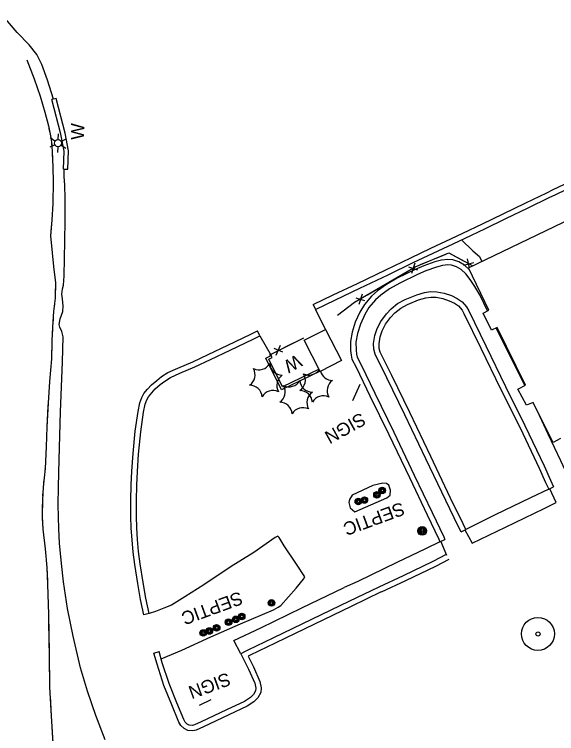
# Model space of a CAD drawing. Extents: x 353423 to 364002, y 127000 to 201942.
# Drawn here: x 358103.2 to 358350.6, y 132514.4 to 132842.4 of the extents above; entities that cross this region are included whole.
import ezdxf

# ---------------------------------------------------------------- set-up
doc = ezdxf.new("R2010")
doc.units = 0
for name, color, linetype in [('E_DTM_SlopeBottom', 7, 'Continuous'), ('E_FEN_Generic', 7, 'Continuous'), ('E_LAND_BrushLine', 7, 'Continuous'), ('E_MISCPROP', 7, 'Continuous'), ('E_RDWY_AsphConc', 7, 'Continuous'), ('E_STRUCT_WingWall', 7, 'Continuous'), ('E_UTL_ETransformer', 7, 'Continuous'), ('E_WTR_FlowLine', 7, 'Continuous')]:
    doc.layers.add(name, color=color, linetype=linetype)

msp = doc.modelspace()

# ---------------------------------------------------------------- linework, layer by layer
at = {"layer": 'E_DTM_SlopeBottom'}
for p, q in [((358309.75, 132730.89), (358310.73, 132726.78)), ((358283.04, 132727.29), (358287.06, 132725.97)), ((358284.53, 132724.41), (358286.1, 132729.08)), ((358308.08, 132728.11), (358312.88, 132729.23)), ((358260.49, 132710.34), (358262.06, 132715.01)), ((358259, 132713.22), (358263.01, 132711.9)), ((358224.4, 132691.39), (358222.52, 132686.83)), ((358225.69, 132688.42), (358221.78, 132690.01))]:
    msp.add_line(p, q, dxfattribs=at)
for points in [[(358125.56, 132771.9), (358127.55, 132771.82), (358127.89, 132780.13), (358126.39, 132788.2), (358122.22, 132804.08), (358120.29, 132803.58)], [(358125.56, 132771.9), (358125.89, 132779.99), (358124.44, 132787.76), (358120.29, 132803.58)], [(358250.63, 132705.29), (358258.41, 132711.14), (358286.06, 132727.32), (358301.4, 132733.63), (358312.39, 132727.79)], [(358298.97, 132732.63), (358301.4, 132733.63), (358307.87, 132730.19)], [(358288.49, 132728.32), (358298.97, 132732.63)], [(358274.06, 132720.3), (358282.65, 132725.33)], [(358264.29, 132714.58), (358274.06, 132720.3)], [(358250.63, 132705.29), (358258.41, 132711.14), (358258.61, 132711.25)], [(358235.12, 132694.79), (358219.65, 132687.08)], [(358235.12, 132694.79), (358226.21, 132690.35)], [(358220.32, 132687.41), (358219.65, 132687.08)], [(358242.68, 132679.75), (358225.08, 132671.21), (358218.01, 132685.68), (358220.35, 132686.82)], [(358242.23, 132680.64), (358225.54, 132672.54), (358219.35, 132685.22), (358220.79, 132685.92), (358220.35, 132686.82)]]:
    msp.add_lwpolyline(points, dxfattribs=at)
at = {"layer": 'E_FEN_Generic'}
for centre, start, end in [((358207.31, 132678.04), 304.2311, 29.996), ((358214.76, 132686.06), 244.2311, 329.996), ((358225.42, 132683.62), 184.2311, 269.996), ((358228.64, 132673.16), 124.2311, 209.996), ((358230.24, 132675.64), 304.2311, 29.996), ((358237.68, 132683.66), 244.2311, 324.9664), ((358248.35, 132681.22), 195.6548, 269.996), ((358228.49, 132678.28), 244.2311, 329.996), ((358239.16, 132675.84), 184.2311, 269.996), ((358251.57, 132670.76), 124.2311, 209.996), ((358210.53, 132667.59), 4.2311, 89.996), ((358221.2, 132665.15), 64.2311, 149.996), ((358221.05, 132670.26), 304.2311, 29.996), ((358233.45, 132665.18), 4.2311, 89.996), ((358242.38, 132665.38), 124.2311, 209.996), ((358244.12, 132662.74), 64.2311, 149.996), ((358224.27, 132659.8), 4.2311, 89.996), ((358234.93, 132657.36), 64.2311, 149.996)]:
    msp.add_arc(centre, 5.72, start, end, dxfattribs=at)
at = {"layer": 'E_LAND_BrushLine'}
for p, q in [((358121.71, 132784.66), (358119.51, 132786.06)), ((358123.17, 132785.37), (358123.28, 132787.89)), ((358124.6, 132784.46), (358126.8, 132785.67)), ((358121.68, 132782.96), (358119.35, 132781.8)), ((358124.53, 132782.83), (358126.7, 132781.43)), ((358123.03, 132782.1), (358122.91, 132779.49))]:
    msp.add_line(p, q, dxfattribs=at)
for points in [[(358257.56, 132666.41), (358261, 132673.76)], [(358192.82, 132529.77), (358187.52, 132527.17)]]:
    msp.add_lwpolyline(points, dxfattribs=at)
for centre, radius in [((358123.12, 132783.73), 1.64), ((358289.27, 132606.88), 2.02), ((358289.26, 132606.88), 1.52), ((358289.3, 132606.88), 1.01), ((358289.29, 132606.89), 0.502)]:
    msp.add_circle(centre, radius, dxfattribs=at)
at = {"layer": 'E_MISCPROP'}
for points in [[(358121.04, 132803.77), (358118.31, 132812.41), (358115.69, 132819.53), (358113.54, 132824.21), (358109.97, 132828.52), (358104.47, 132834.22), (358097.51, 132842.43)], [(358349.06, 132762.58), (358353.93, 132764.89), (358364.31, 132769.86), (358374.69, 132775.32), (358385.91, 132780.9), (358398.31, 132787.41)], [(358350.19, 132760.35), (358355.01, 132762.63), (358365.43, 132767.63), (358375.83, 132773.1), (358387.04, 132778.68), (358399.47, 132785.2)], [(358125.68, 132583.63), (358124.69, 132591.98), (358123.84, 132601.24), (358123.45, 132607.8), (358123.15, 132618.76), (358123.28, 132626.98), (358123.71, 132639.38), (358124.23, 132661.2), (358125.18, 132683.94), (358125.43, 132695.39), (358124.88, 132697.8), (358123.98, 132699.72), (358123.71, 132701.05), (358124.11, 132703.62), (358125.31, 132706.97), (358125.46, 132709.29), (358125.16, 132712.74), (358124.93, 132714.9), (358125.13, 132717.22), (358125.56, 132719), (358125.9, 132723.23), (358126.19, 132738.95), (358126.33, 132748.46), (358126.32, 132758.42), (358126.22, 132764.56), (358126.01, 132768.54), (358125.93, 132771.88)], [(358307.76, 132742.63), (358316.71, 132746.94), (358326.27, 132751.54), (358336.58, 132756.51), (358346.15, 132761.1), (358349.06, 132762.58)], [(358308.83, 132740.37), (358317.79, 132744.68), (358327.36, 132749.29), (358337.67, 132754.26), (358347.26, 132758.86), (358350.19, 132760.35)], [(358239.57, 132710.09), (358248.66, 132714.48), (358259.8, 132719.77), (358272.69, 132725.9), (358284.13, 132731.45), (358293.15, 132735.74), (358302.26, 132740.03), (358307.76, 132742.63)], [(358239.57, 132710.09), (358240.66, 132707.84), (358249.74, 132712.22), (358260.88, 132717.51), (358273.77, 132723.64), (358285.21, 132729.2), (358294.22, 132733.48), (358303.33, 132737.77), (358308.83, 132740.37)], [(358307.24, 132739.62), (358312.42, 132734.58), (358315.38, 132731.94), (358316.49, 132729.77)], [(358310.86, 132725.92), (358308.56, 132728.03), (358306.03, 132729.57), (358303.19, 132730.5), (358300.97, 132730.66), (358298.11, 132730.35), (358295.01, 132729.58), (358290.01, 132727.75), (358286.11, 132726.04), (358277.83, 132722.09), (358272.95, 132719.3), (358268.81, 132716.36), (358266.16, 132713.94), (358262.96, 132710.15), (358260.82, 132706.67), (358258.75, 132702.07), (358257.27, 132697.5), (358256.55, 132693.2), (358256.59, 132689.18), (358256.82, 132687.05), (358257.24, 132685.21), (358259.17, 132681.53), (358265.34, 132668.53), (358274.03, 132650.79), (358283.41, 132631.23), (358291.56, 132614.26), (358296.83, 132603.09), (358297.31, 132601.93), (358299.62, 132602.89)], [(358319.13, 132707.25), (358315.54, 132714.51), (358313.27, 132718.37), (358311.19, 132721.55), (358309.17, 132724.08), (358307.05, 132726.02), (358304.98, 132727.28), (358302.71, 132728.03), (358301.02, 132728.15), (358298.55, 132727.88), (358295.74, 132727.18), (358290.95, 132725.43), (358287.15, 132723.77), (358278.99, 132719.87), (358274.3, 132717.19), (358270.38, 132714.42), (358267.97, 132712.21), (358264.99, 132708.68), (358263.03, 132705.49), (358261.09, 132701.17), (358259.71, 132696.9), (358259.05, 132693), (358259.09, 132689.33), (358259.29, 132687.47), (358259.6, 132686.09), (358261.41, 132682.65), (358267.59, 132669.61), (358276.28, 132651.89), (358285.66, 132632.31), (358293.82, 132615.33), (358299.12, 132604.1), (358299.62, 132602.89)], [(358307, 132606.38), (358305.69, 132608.98), (358300, 132620.76), (358290.95, 132639.66), (358281.33, 132659.76), (358273.09, 132676.65), (358267.82, 132687.45), (358267.19, 132689.72), (358267.07, 132692.34), (358267.62, 132696.05), (358268.76, 132699.13), (358270.45, 132702.43), (358272.93, 132705.82), (358275.04, 132708.11), (358278.06, 132710.53), (358281.52, 132712.41), (358286.76, 132714.6), (358290.34, 132715.63), (358293.05, 132716.02), (358295.97, 132715.94), (358299.28, 132715.27), (358302.58, 132714.16), (358305.22, 132712.9), (358307.51, 132711.35), (358309.47, 132709.01), (358310.53, 132707.25), (358318.24, 132691.27), (358327.29, 132672.76), (358336.15, 132654.93), (358344.86, 132636.58), (358347.73, 132630.01), (358349.21, 132627)], [(358307, 132606.38), (358309.23, 132607.5), (358307.93, 132610.08), (358302.25, 132621.84), (358293.2, 132640.74), (358283.58, 132660.85), (358275.34, 132677.74), (358270.16, 132688.34), (358269.67, 132690.12), (358269.57, 132692.21), (358270.05, 132695.43), (358271.05, 132698.12), (358272.59, 132701.11), (358274.86, 132704.23), (358276.75, 132706.28), (358279.45, 132708.44), (358282.6, 132710.15), (358287.59, 132712.24), (358290.86, 132713.18), (358293.2, 132713.51), (358295.68, 132713.45), (358298.63, 132712.85), (358301.64, 132711.84), (358303.97, 132710.72), (358305.82, 132709.48), (358307.43, 132707.55), (358308.33, 132706.05), (358315.99, 132690.18), (358325.05, 132671.66), (358333.91, 132653.84), (358342.58, 132635.54), (358345.46, 132628.95), (358346.97, 132625.89), (358349.21, 132627)], [(358240.66, 132707.84), (358243.34, 132702.21), (358245.11, 132698.76)], [(358159.48, 132582.92), (358158.17, 132591.49), (358157.38, 132597.24), (358156.89, 132602.8), (358156.57, 132608.08), (358156.37, 132613.56), (358156.42, 132620.75), (358156.53, 132627.84), (358156.85, 132634.1), (358157.43, 132642.12), (358158.4, 132652.42), (358159.67, 132661.39), (358160.45, 132665.3), (358161.31, 132667.66), (358162.33, 132669.46), (358163.99, 132671.54), (358165.78, 132673.44), (358168.15, 132675.53), (358170.4, 132677.22), (358173.3, 132679.05), (358177.72, 132681.03), (358184.56, 132683.99), (358191.61, 132687.31), (358200.66, 132691.59), (358211.02, 132696.56), (358214.16, 132698.05)], [(358161.95, 132583.3), (358160.65, 132591.85), (358159.87, 132597.52), (358159.38, 132602.99), (358159.06, 132608.2), (358158.87, 132613.59), (358158.92, 132620.73), (358159.03, 132627.76), (358159.34, 132633.94), (358159.92, 132641.92), (358160.88, 132652.12), (358162.14, 132660.97), (358162.87, 132664.63), (358163.58, 132666.61), (358164.41, 132668.05), (358165.89, 132669.9), (358167.52, 132671.64), (358169.72, 132673.58), (358171.82, 132675.16), (358174.48, 132676.84), (358178.73, 132678.74), (358185.59, 132681.71), (358192.68, 132685.05), (358201.74, 132689.33), (358212.1, 132694.3), (358215.23, 132695.79), (358214.16, 132698.05)], [(358336.04, 132673.13), (358322.99, 132699.46)], [(358215.23, 132695.79), (358220.35, 132686.82)], [(358356.48, 132630.37), (358355.81, 132631.7), (358352.52, 132638.85), (358346.75, 132650.94), (358342.83, 132659.44), (358339.86, 132665.43)], [(358308.79, 132607.28), (358312.02, 132601.2), (358327.27, 132608.57), (358344.96, 132617.14), (358350.34, 132619.78), (358347.42, 132626.12)], [(358346.97, 132625.89), (358338.75, 132621.88), (358322.57, 132614.12), (358311.3, 132608.64), (358309.23, 132607.5)], [(358235.72, 132585.91), (358231.85, 132591.76), (358226.33, 132600.1), (358223.98, 132603.9), (358223.47, 132604.45), (358222.15, 132603.91), (358212.44, 132597), (358202.19, 132590.56), (358189.67, 132582.27), (358180.95, 132576.76), (358174.84, 132573.02), (358171.47, 132571.68), (358167.63, 132570.05), (358164.66, 132569.19)], [(358297.31, 132601.93), (358290.76, 132598.68), (358277.66, 132592.52), (358259.93, 132583.83), (358253.72, 132580.98)], [(358300.48, 132595.66), (358297.77, 132602.12)], [(358300.25, 132596.11), (358294.17, 132592.9), (358280.54, 132586.41), (358269.49, 132581.27)], [(358301.42, 132593.89), (358295.29, 132590.66), (358281.6, 132584.15), (358270.55, 132579)], [(358170.2, 132548.46), (358179.55, 132552.48), (358192.86, 132558.6), (358206.43, 132564.54), (358221.45, 132570.86), (358223.59, 132572.04), (358224.78, 132572.84), (358231.73, 132580.74), (358235.16, 132584.89), (358235.72, 132585.91)], [(358144.66, 132511.56), (358140.32, 132522.65), (358136.56, 132533.82), (358133.41, 132544.48), (358129.98, 132558.88), (358127.42, 132571.45), (358125.68, 132583.63)], [(358164.66, 132569.19), (358162.21, 132568.66), (358160.72, 132575.65), (358159.48, 132582.89)], [(358164.66, 132569.19), (358163.17, 132576.12), (358161.95, 132583.31)], [(358270.57, 132579.01), (358256.83, 132572.38), (358240.1, 132564.38), (358222.17, 132555.7), (358210.86, 132550.27), (358209.85, 132549.71), (358212.26, 132544.81), (358215.25, 132538.14), (358215.84, 132535.27), (358215.7, 132533.15), (358214.35, 132530.73), (358212.49, 132528.89), (358209.39, 132526.94), (358201, 132523), (358189.55, 132517.54), (358186.12, 132515.97), (358184.57, 132515.67), (358182.31, 132515.81), (358180.62, 132516.7), (358179.2, 132518.08), (358178.28, 132519.67), (358175.01, 132527.49), (358171.46, 132536.39), (358168.31, 132546.03), (358166.8, 132551.18), (358169.21, 132551.88)], [(358269.49, 132581.26), (358255.74, 132574.64), (358239.01, 132566.63), (358221.08, 132557.95), (358209.72, 132552.49), (358208.57, 132551.86), (358206.5, 132550.85), (358209.99, 132543.75), (358212.86, 132537.36), (358213.33, 132535.1), (358213.24, 132533.87), (358212.34, 132532.25), (358210.93, 132530.86), (358208.18, 132529.14), (358199.93, 132525.26), (358188.49, 132519.81), (358185.35, 132518.37), (358184.41, 132518.18), (358183.01, 132518.27), (358182.1, 132518.75), (358181.19, 132519.63), (358180.53, 132520.78), (358177.32, 132528.43), (358173.82, 132537.24), (358170.7, 132546.77), (358169.21, 132551.88)], [(358206.5, 132550.85), (358203.35, 132556.91), (358215.6, 132562.65), (358234.34, 132571.75), (358253.72, 132580.98)]]:
    msp.add_lwpolyline(points, dxfattribs=at)
for points in [[(358219.33, 132573.87), (358219.41, 132574.42), (358219.59, 132574.68), (358220.06, 132575.06), (358220.61, 132575.18), (358221.08, 132575.14), (358221.5, 132574.83), (358221.88, 132574.24), (358221.88, 132573.51), (358221.53, 132573.05), (358220.72, 132572.67), (358220.04, 132572.76), (358219.58, 132573.1)], [(358199.82, 132565.03), (358199.91, 132565.58), (358200.09, 132565.84), (358200.56, 132566.22), (358201.11, 132566.34), (358201.58, 132566.3), (358202, 132565.99), (358202.38, 132565.4), (358202.37, 132564.67), (358202.03, 132564.21), (358201.22, 132563.83), (358200.54, 132563.92), (358200.07, 132564.26)], [(358194.4, 132562.52), (358194.49, 132563.07), (358194.66, 132563.32), (358195.14, 132563.7), (358195.69, 132563.83), (358196.16, 132563.78), (358196.58, 132563.48), (358196.96, 132562.88), (358196.95, 132562.16), (358196.61, 132561.69), (358195.8, 132561.32), (358195.12, 132561.41), (358194.65, 132561.75)]]:
    msp.add_lwpolyline(points, close=True, dxfattribs=at)
at = {"layer": 'E_RDWY_AsphConc'}
for radius in [7.5, 7.5, 7.5, 7.5, 0.96, 0.96, 0.96, 0.96]:
    msp.add_circle((358342.07, 132559.87), radius, dxfattribs=at)
at = {"layer": 'E_STRUCT_WingWall'}
for points in [[(358108.92, 132821.77), (358112.23, 132813.06), (358114.97, 132805.07), (358117.09, 132797.78), (358118.72, 132791.66), (358120.07, 132785.55), (358120.47, 132780.02), (358120.8, 132772.59), (358120.86, 132766.16), (358120.75, 132756.2), (358120.38, 132748.61), (358119.72, 132741.44), (358120.42, 132733.67), (358121.1, 132727.48), (358121.94, 132719.96), (358121.86, 132713.03), (358121.09, 132706.89), (358120.68, 132699.76), (358120.36, 132693.5), (358120.15, 132685.41), (358119.29, 132675.04), (358118.57, 132665.13), (358117.99, 132654.35), (358117.73, 132645.22), (358117.21, 132635.27), (358116.33, 132626.85), (358116.02, 132621), (358115.85, 132613.49), (358116.2, 132607.64), (358117.27, 132598.75), (358118.01, 132590.23), (358118.4, 132582.5)], [(358108.92, 132821.77), (358112.23, 132813.06), (358114.97, 132805.07), (358117.09, 132797.78), (358118.03, 132794.26)], [(358119.01, 132790.38), (358119.43, 132788.43)], [(358120.14, 132784.5), (358120.29, 132782.51)], [(358120.53, 132778.51), (358120.62, 132776.52)], [(358120.8, 132772.52), (358120.86, 132766.16), (358120.75, 132756.2), (358120.38, 132748.61), (358119.91, 132743.55)], [(358119.91, 132743.55), (358119.72, 132741.44), (358120.42, 132733.67), (358121.1, 132727.48), (358121.94, 132719.96), (358121.88, 132714.67)], [(358121.57, 132710.69), (358121.32, 132708.71)], [(358120.97, 132704.73), (358120.85, 132702.73)], [(358120.63, 132698.74), (358120.53, 132696.74)], [(358120.35, 132692.74), (358120.15, 132685.41), (358119.29, 132675.04), (358118.57, 132665.13), (358118.49, 132663.81)], [(358118.49, 132663.81), (358117.99, 132654.35), (358117.73, 132645.22), (358117.21, 132635.27), (358117.16, 132634.84)], [(358116.75, 132630.86), (358116.54, 132628.88)], [(358116.22, 132624.89), (358116.12, 132622.89)], [(358115.97, 132618.89), (358115.92, 132616.89)], [(358115.89, 132612.9), (358116.2, 132607.64), (358117.27, 132598.75), (358118.01, 132590.23), (358118.33, 132584.01)], [(358118.33, 132584.01), (358118.4, 132582.5)], [(358118.4, 132582.5), (358118.73, 132568.67), (358119.04, 132551.36), (358119.27, 132535.53), (358119.98, 132522.51), (358121.21, 132502.38), (358121.74, 132481.96), (358121.21, 132466.01), (358121.37, 132453.16), (358121.65, 132444.1), (358121.43, 132425), (358121.9, 132412.02), (358121.73, 132399.64), (358122.31, 132385.43), (358122.83, 132374.45), (358123.01, 132364.33), (358122.13, 132354.08), (358122.06, 132343.75), (358122.64, 132335.19), (358122.89, 132328.51), (358123.75, 132323.66), (358124.74, 132319.35), (358127.11, 132317.04), (358130.2, 132315.27)], [(358118.4, 132582.5), (358118.73, 132568.67), (358119, 132553.51)], [(358119.06, 132549.51), (358119.09, 132547.51)], [(358119.15, 132543.51), (358119.18, 132541.51)], [(358119.24, 132537.51), (358119.27, 132535.53), (358119.27, 132535.51)], [(358119.49, 132531.52), (358119.98, 132522.51), (358121.2, 132502.57)]]:
    msp.add_lwpolyline(points, dxfattribs=at)
at = {"layer": 'E_UTL_ETransformer'}
for centre, radius in [((358271.06, 132625.33), 1.5), ((358271.06, 132625.34), 1.22), ((358271.08, 132625.33), 0.968), ((358271.08, 132625.3), 0.605), ((358260.13, 132620.22), 1.5), ((358262.88, 132620.94), 1.5), ((358262.88, 132620.94), 1.22), ((358262.89, 132620.94), 0.968), ((358268.63, 132623.29), 1.5), ((358268.63, 132623.29), 1.22), ((358268.65, 132623.28), 0.968), ((358268.65, 132623.26), 0.605), ((358260.13, 132620.23), 1.22), ((358260.15, 132620.22), 0.968), ((358260.15, 132620.19), 0.605), ((358262.9, 132620.91), 0.605), ((358220.5, 132574.01), 1.5), ((358220.51, 132574.02), 1.22), ((358220.52, 132574.01), 0.968), ((358220.53, 132573.98), 0.605), ((358206.93, 132567.85), 1.5), ((358200.92, 132565.26), 1.5), ((358200.92, 132565.26), 1.22), ((358200.93, 132565.25), 0.968), ((358204.2, 132566.55), 1.5), ((358204.2, 132566.56), 1.22), ((358204.22, 132566.55), 0.968), ((358204.22, 132566.52), 0.605), ((358206.94, 132567.86), 1.22), ((358206.95, 132567.85), 0.968), ((358206.96, 132567.82), 0.605), ((358192.17, 132561.23), 1.5), ((358195.5, 132562.66), 1.5), ((358195.5, 132562.66), 1.22), ((358195.51, 132562.65), 0.968), ((358195.52, 132562.63), 0.605), ((358200.94, 132565.23), 0.605), ((358189.4, 132560.32), 1.5), ((358189.4, 132560.32), 1.22), ((358189.41, 132560.31), 0.968), ((358189.42, 132560.29), 0.605), ((358192.17, 132561.24), 1.22), ((358192.18, 132561.23), 0.968), ((358192.19, 132561.2), 0.605)]:
    msp.add_circle(centre, radius, dxfattribs=at)
at = {"layer": 'E_WTR_FlowLine'}
msp.add_lwpolyline([(358352.35, 132648.94), (358349.01, 132647.24), (358339.95, 132665.47), (358336.9, 132664.2), (358332.95, 132671.44), (358336.35, 132673.3), (358323.4, 132699.66), (358320.9, 132698.43), (358317.12, 132706.16), (358319.73, 132707.58), (358310.42, 132726.84), (358361.28, 132751.37)], dxfattribs=at)
for points in [[(358245.17, 132698.79), (358252.44, 132684.6), (358242.75, 132679.63), (358235.47, 132693.82)], [(358258.53, 132615.52), (358273.1, 132621.92), (358274.68, 132623.2), (358274.86, 132625.51), (358274.04, 132627.69), (358273, 132628.45), (358271.3, 132628.62), (358266.81, 132627.52), (358257.31, 132623.18), (358256.17, 132621.18), (358255.83, 132619.76), (358256.43, 132617.41)]]:
    msp.add_lwpolyline(points, close=True, dxfattribs=at)

# ---------------------------------------------------------------- texts
at = {"layer": 'E_DTM_SlopeBottom'}
for rotation, p in [(89.0198, (358134.98, 132785.16)), (209.0197, (358232.13, 132687.58))]:
    msp.add_text('W', height=6, rotation=rotation, dxfattribs=at).set_placement(p)
at = {"layer": 'E_LAND_BrushLine'}
for rotation, p in [(209.0197, (358261.31, 132661.06)), (200.1741, (358200.47, 132542.44))]:
    msp.add_text('SIGN', height=6, rotation=rotation, dxfattribs=at).set_placement(p)
at = {"layer": 'E_UTL_ETransformer'}
for p in [(358279.87, 132620.15), (358206.01, 132579.4)]:
    msp.add_text('SEPTIC', height=6, rotation=200.1741, dxfattribs=at).set_placement(p)

doc.saveas('drawing.dxf')
